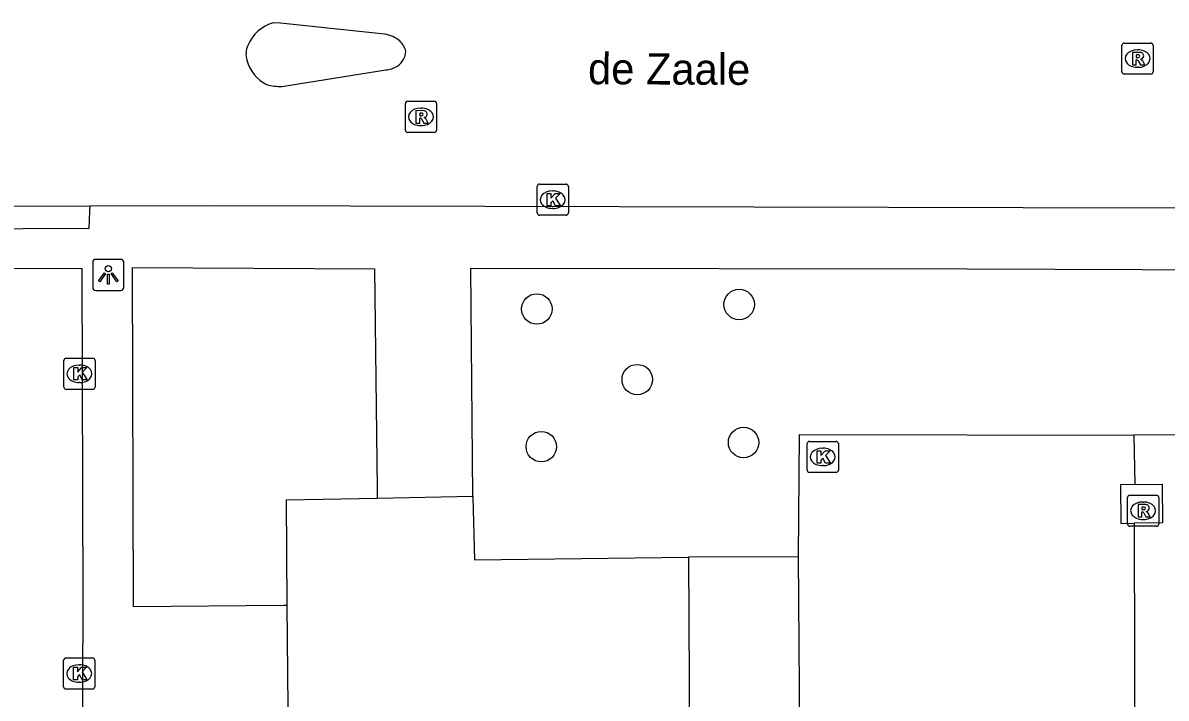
# Model space of a CAD drawing. Extents: x 161477 to 163040, y 383680 to 384868.
# Drawn here: x 161812.22 to 161848.92, y 384356.35 to 384378.03 of the extents above; entities that cross this region are included whole.
import ezdxf

# ---------------------------------------------------------------- set-up
doc = ezdxf.new("R2010")
doc.units = 0
for name, color, linetype in [('IMGEO_Boom', 7, 'Continuous'), ('IMGEO_Groenvoorziening', 7, 'Continuous'), ('IMGEO_Kolk', 7, 'Continuous'), ('IMGEO_Lichtpunt', 7, 'Continuous'), ('IMGEO_Openbare_ruimte_label', 7, 'Continuous'), ('IMGEO_Rijbaan_lokaal_open', 7, 'Continuous'), ('IMGEO_Rioolput', 7, 'Continuous'), ('IMGEO_Voetpad_gesloten', 7, 'Continuous'), ('IMGEO_Voetpad_op_trap', 7, 'Continuous'), ('IMGEO_Voetpad_open', 7, 'Continuous')]:
    doc.layers.add(name, color=color, linetype=linetype)

msp = doc.modelspace()

# ---------------------------------------------------------------- linework, layer by layer
at = {"layer": 'IMGEO_Boom'}
for centre in [(161835.213, 384368.986), (161828.719, 384368.843), (161831.942, 384366.577), (161828.862, 384364.424), (161835.355, 384364.556)]:
    msp.add_circle(centre, 0.489, dxfattribs=at)
at = {"layer": 'IMGEO_Groenvoorziening'}
msp.add_lwpolyline([(161866.104, 384364.813), (161847.882, 384364.794)], dxfattribs=at)
at = {"layer": 'IMGEO_Kolk'}
for p, q in [((161828.804, 384372.851), (161829.656, 384372.851)), ((161828.729, 384371.925), (161828.729, 384372.777)), ((161829.217, 384372.631), (161829.242, 384372.631)), ((161829.73, 384372.777), (161829.73, 384371.925)), ((161829.24, 384372.071), (161829.215, 384372.071)), ((161829.656, 384371.851), (161828.804, 384371.851)), ((161813.538, 384366.338), (161813.538, 384367.19)), ((161813.613, 384367.264), (161814.465, 384367.264)), ((161814.026, 384367.044), (161814.051, 384367.044)), ((161814.539, 384367.19), (161814.539, 384366.338)), ((161814.465, 384366.264), (161813.613, 384366.264)), ((161814.049, 384366.484), (161814.024, 384366.484)), ((161837.395, 384363.669), (161837.395, 384364.521)), ((161837.47, 384364.595), (161838.322, 384364.595)), ((161837.883, 384364.375), (161837.908, 384364.375)), ((161838.396, 384364.521), (161838.396, 384363.669)), ((161837.906, 384363.815), (161837.881, 384363.815)), ((161838.322, 384363.595), (161837.47, 384363.595)), ((161813.531, 384356.717), (161813.531, 384357.569)), ((161813.606, 384357.643), (161814.458, 384357.643)), ((161814.019, 384357.423), (161814.044, 384357.423)), ((161814.532, 384357.569), (161814.532, 384356.717)), ((161814.458, 384356.643), (161813.606, 384356.643)), ((161814.042, 384356.863), (161814.017, 384356.863))]:
    msp.add_line(p, q, dxfattribs=at)
for points in [[(161828.804, 384372.851), (161829.656, 384372.851)], [(161828.729, 384371.925), (161828.729, 384372.777)], [(161829.05, 384372.551), (161829.173, 384372.551), (161829.173, 384372.4), (161829.303, 384372.551), (161829.467, 384372.551), (161829.321, 384372.4), (161829.474, 384372.151), (161829.322, 384372.151), (161829.237, 384372.315), (161829.173, 384372.248), (161829.173, 384372.151), (161829.05, 384372.151), (161829.05, 384372.551)], [(161829.73, 384372.777), (161829.73, 384371.925)], [(161829.656, 384371.851), (161828.804, 384371.851)], [(161813.538, 384366.338), (161813.538, 384367.19)], [(161813.613, 384367.264), (161814.465, 384367.264)], [(161813.859, 384366.964), (161813.982, 384366.964), (161813.982, 384366.813), (161814.112, 384366.964), (161814.276, 384366.964), (161814.13, 384366.813), (161814.283, 384366.564), (161814.131, 384366.564), (161814.046, 384366.728), (161813.982, 384366.661), (161813.982, 384366.564), (161813.859, 384366.564), (161813.859, 384366.964)], [(161814.539, 384367.19), (161814.539, 384366.338)], [(161814.465, 384366.264), (161813.613, 384366.264)], [(161837.395, 384363.669), (161837.395, 384364.521)], [(161837.47, 384364.595), (161838.322, 384364.595)], [(161838.396, 384364.521), (161838.396, 384363.669)], [(161837.716, 384364.295), (161837.839, 384364.295), (161837.839, 384364.144), (161837.969, 384364.295), (161838.133, 384364.295), (161837.987, 384364.144), (161838.14, 384363.895), (161837.988, 384363.895), (161837.903, 384364.059), (161837.839, 384363.992), (161837.839, 384363.895), (161837.716, 384363.895), (161837.716, 384364.295)], [(161838.322, 384363.595), (161837.47, 384363.595)], [(161813.531, 384356.717), (161813.531, 384357.569)], [(161813.606, 384357.643), (161814.458, 384357.643)], [(161814.532, 384357.569), (161814.532, 384356.717)], [(161813.852, 384357.343), (161813.975, 384357.343), (161813.975, 384357.192), (161814.105, 384357.343), (161814.269, 384357.343), (161814.123, 384357.192), (161814.276, 384356.943), (161814.124, 384356.943), (161814.039, 384357.107), (161813.975, 384357.04), (161813.975, 384356.943), (161813.852, 384356.943), (161813.852, 384357.343)], [(161814.458, 384356.643), (161813.606, 384356.643)]]:
    msp.add_lwpolyline(points, dxfattribs=at)
for centre, start, end in [((161828.806, 384372.775), 91.552, 178.448), ((161828.806, 384372.775), 91.552, 178.448), ((161829.654, 384372.775), 1.552, 88.448), ((161829.654, 384372.775), 1.552, 88.448), ((161828.806, 384371.927), 181.552, 268.448), ((161828.806, 384371.927), 181.552, 268.448), ((161829.654, 384371.927), 271.552, 358.448), ((161829.654, 384371.927), 271.552, 358.448), ((161813.615, 384367.188), 91.552, 178.448), ((161813.615, 384367.188), 91.552, 178.448), ((161814.463, 384367.188), 1.552, 88.448), ((161814.463, 384367.188), 1.552, 88.448), ((161813.615, 384366.34), 181.552, 268.448), ((161813.615, 384366.34), 181.552, 268.448), ((161814.463, 384366.34), 271.552, 358.448), ((161814.463, 384366.34), 271.552, 358.448), ((161837.472, 384364.519), 91.552, 178.448), ((161837.472, 384364.519), 91.552, 178.448), ((161838.32, 384364.519), 1.552, 88.448), ((161838.32, 384364.519), 1.552, 88.448), ((161837.472, 384363.671), 181.552, 268.448), ((161837.472, 384363.671), 181.552, 268.448), ((161838.32, 384363.671), 271.552, 358.448), ((161838.32, 384363.671), 271.552, 358.448), ((161813.608, 384357.567), 91.552, 178.448), ((161813.608, 384357.567), 91.552, 178.448), ((161814.456, 384357.567), 1.552, 88.448), ((161814.456, 384357.567), 1.552, 88.448), ((161813.608, 384356.719), 181.552, 268.448), ((161813.608, 384356.719), 181.552, 268.448), ((161814.456, 384356.719), 271.552, 358.448), ((161814.456, 384356.719), 271.552, 358.448)]:
    msp.add_arc(centre, 0.0765, start, end, dxfattribs=at)
for centre, major_axis, ratio, start_param, end_param in [((161829.216, 384372.351), (-0.387, 0.002), 0.722429, 4.712389, 7.853982), ((161829.241, 384372.351), (-0.39, 0.002), 0.717154, 1.570796, 4.712389), ((161814.025, 384366.764), (-0.387, 0.002), 0.722429, 4.712389, 7.853982), ((161814.05, 384366.764), (-0.39, 0.002), 0.717154, 1.570796, 4.712389), ((161837.882, 384364.095), (-0.387, 0.002), 0.722429, 4.712389, 7.853982), ((161837.907, 384364.095), (-0.39, 0.002), 0.717154, 1.570796, 4.712389), ((161814.018, 384357.143), (-0.387, 0.002), 0.722429, 4.712389, 7.853982), ((161814.043, 384357.143), (-0.39, 0.002), 0.717154, 1.570796, 4.712389)]:
    msp.add_ellipse(centre, major_axis=major_axis, ratio=ratio, start_param=start_param, end_param=end_param, dxfattribs=at)
at = {"layer": 'IMGEO_Lichtpunt'}
for p, q in [((161814.466, 384370.342), (161814.466, 384369.535)), ((161814.466, 384370.342), (161814.466, 384369.535)), ((161815.368, 384370.437), (161814.56, 384370.437)), ((161815.368, 384370.437), (161814.56, 384370.437)), ((161815.462, 384369.535), (161815.462, 384370.342)), ((161815.462, 384369.535), (161815.462, 384370.342)), ((161814.56, 384369.441), (161815.368, 384369.441)), ((161814.56, 384369.441), (161815.368, 384369.441))]:
    msp.add_line(p, q, dxfattribs=at)
for points in [[(161814.84, 384370.006), (161814.879, 384369.978), (161814.691, 384369.716), (161814.653, 384369.743), (161814.84, 384370.006)], [(161814.942, 384369.958), (161814.989, 384369.958), (161814.989, 384369.636), (161814.942, 384369.636), (161814.942, 384369.958)], [(161815.052, 384369.978), (161815.09, 384370.005), (161815.277, 384369.743), (161815.238, 384369.715), (161815.052, 384369.978)]]:
    msp.add_lwpolyline(points, dxfattribs=at)
msp.add_circle((161814.965, 384370.14), 0.0994, dxfattribs=at)
for centre, start, end in [((161814.56, 384370.342), 90, 180), ((161814.56, 384370.342), 90, 180), ((161815.368, 384370.342), 0, 90), ((161815.368, 384370.342), 0, 90), ((161814.56, 384369.535), 180, 270), ((161814.56, 384369.535), 180, 270), ((161815.368, 384369.535), 270, 0), ((161815.368, 384369.535), 270, 360)]:
    msp.add_arc(centre, 0.0946, start, end, dxfattribs=at)
at = {"layer": 'IMGEO_Rijbaan_lokaal_open'}
for points in [[(161823.835, 384377.663), (161820.487, 384378.015), (161820.257, 384378.027)], [(161820.537, 384375.987), (161823.868, 384376.515)], [(161814.368, 384372.145), (161807.983, 384372.135)], [(161861.126, 384372.071), (161844.332, 384372.085), (161818.41, 384372.152), (161814.368, 384372.145)], [(161814.035, 384329.719), (161814.102, 384340.861), (161814.121, 384351.376), (161814.162, 384359.441), (161814.131, 384370.138), (161807.989, 384370.133)]]:
    msp.add_lwpolyline(points, dxfattribs=at)
for centre, radius, start, end in [((161820.613, 384376.806), 1.272, 106.2566, 156.888), ((161823.687, 384376.676), 0.998, 50.3941, 81.4633), ((161820.099, 384377.02), 0.716, 156.4919, 195.6095), ((161823.804, 384376.919), 0.739, 14.8896, 45.3685), ((161820.613, 384377.16), 1.249, 195.4874, 243.0755), ((161823.868, 384377.17), 0.653, 305.2923, 354.6184), ((161823.753, 384377.513), 1.005, 276.5601, 299.3038), ((161820.48, 384377.543), 1.557, 253.9011, 272.1085)]:
    msp.add_arc(centre, radius, start, end, dxfattribs=at)
at = {"layer": 'IMGEO_Rioolput'}
for p, q in [((161847.499, 384376.454), (161847.499, 384377.306)), ((161847.574, 384377.38), (161848.426, 384377.38)), ((161848.5, 384377.306), (161848.5, 384376.454)), ((161847.987, 384377.16), (161848.012, 384377.16)), ((161848.01, 384376.6), (161847.985, 384376.6)), ((161848.426, 384376.38), (161847.574, 384376.38)), ((161824.499, 384374.584), (161824.499, 384375.436)), ((161824.574, 384375.51), (161825.426, 384375.51)), ((161825.5, 384375.436), (161825.5, 384374.584)), ((161824.987, 384375.29), (161825.012, 384375.29)), ((161825.01, 384374.73), (161824.985, 384374.73)), ((161825.426, 384374.51), (161824.574, 384374.51)), ((161847.678, 384361.942), (161847.678, 384362.794)), ((161847.753, 384362.868), (161848.605, 384362.868)), ((161848.166, 384362.648), (161848.191, 384362.648)), ((161848.679, 384362.794), (161848.679, 384361.942)), ((161848.605, 384361.868), (161847.753, 384361.868)), ((161848.189, 384362.088), (161848.164, 384362.088))]:
    msp.add_line(p, q, dxfattribs=at)
for points in [[(161847.499, 384376.454), (161847.499, 384377.306)], [(161847.574, 384377.38), (161848.426, 384377.38)], [(161848.5, 384377.306), (161848.5, 384376.454)], [(161848.088, 384377.078), (161847.836, 384377.08), (161847.836, 384376.68)], [(161847.836, 384376.68), (161847.96, 384376.68), (161847.96, 384376.842), (161847.971, 384376.842)], [(161848.014, 384376.999), (161847.96, 384376.999), (161847.96, 384376.918)], [(161847.96, 384376.918), (161848.012, 384376.918)], [(161848.018, 384376.813), (161848.089, 384376.68), (161848.229, 384376.68), (161848.164, 384376.806)], [(161848.426, 384376.38), (161847.574, 384376.38)], [(161824.499, 384374.584), (161824.499, 384375.436)], [(161824.574, 384375.51), (161825.426, 384375.51)], [(161825.5, 384375.436), (161825.5, 384374.584)], [(161825.088, 384375.208), (161824.836, 384375.21), (161824.836, 384374.81)], [(161825.014, 384375.129), (161824.96, 384375.129), (161824.96, 384375.048)], [(161824.96, 384375.048), (161825.012, 384375.048)], [(161824.836, 384374.81), (161824.96, 384374.81), (161824.96, 384374.972), (161824.971, 384374.972)], [(161825.018, 384374.943), (161825.089, 384374.81), (161825.229, 384374.81), (161825.164, 384374.936)], [(161825.426, 384374.51), (161824.574, 384374.51)], [(161847.678, 384361.942), (161847.678, 384362.794)], [(161847.753, 384362.868), (161848.605, 384362.868)], [(161848.267, 384362.566), (161848.015, 384362.568), (161848.015, 384362.168)], [(161848.679, 384362.794), (161848.679, 384361.942)], [(161848.015, 384362.168), (161848.139, 384362.168), (161848.139, 384362.33), (161848.15, 384362.33)], [(161848.193, 384362.487), (161848.139, 384362.487), (161848.139, 384362.406)], [(161848.139, 384362.406), (161848.191, 384362.406)], [(161848.197, 384362.301), (161848.268, 384362.168), (161848.408, 384362.168), (161848.343, 384362.294)], [(161848.605, 384361.868), (161847.753, 384361.868)]]:
    msp.add_lwpolyline(points, dxfattribs=at)
for centre, radius, start, end in [((161847.576, 384377.304), 0.0765, 91.552, 178.448), ((161847.576, 384377.304), 0.0765, 91.552, 178.448), ((161848.424, 384377.304), 0.0765, 1.552, 88.448), ((161848.424, 384377.304), 0.0765, 1.552, 88.448), ((161847.97, 384376.789), 0.0533, 26.0293, 88.6989), ((161847.996, 384377.107), 0.19, 274.7715, 282.9687), ((161848.02, 384376.903), 0.0964, 77.0061, 93.1865), ((161848.034, 384376.96), 0.0378, 276.6634, 79.6772), ((161848.087, 384376.968), 0.109, 350.3612, 89.416), ((161848.085, 384376.968), 0.112, 277.5842, 350.9817), ((161848.069, 384376.753), 0.108, 29.5134, 73.7905), ((161847.576, 384376.456), 0.0765, 181.552, 268.448), ((161847.576, 384376.456), 0.0765, 181.552, 268.448), ((161848.424, 384376.456), 0.0765, 271.552, 358.448), ((161848.424, 384376.456), 0.0765, 271.552, 358.448), ((161824.576, 384375.434), 0.0765, 91.552, 178.448), ((161824.576, 384375.434), 0.0765, 91.552, 178.448), ((161825.424, 384375.434), 0.0765, 1.552, 88.448), ((161825.424, 384375.434), 0.0765, 1.552, 88.448), ((161824.996, 384375.237), 0.19, 274.7715, 282.9687), ((161825.02, 384375.033), 0.0964, 77.0061, 93.1865), ((161825.034, 384375.09), 0.0378, 276.6634, 79.6772), ((161825.087, 384375.098), 0.109, 350.3612, 89.416), ((161825.085, 384375.098), 0.112, 277.5842, 350.9817), ((161825.069, 384374.883), 0.108, 29.5134, 73.7905), ((161824.97, 384374.919), 0.0533, 26.0293, 88.6989), ((161824.576, 384374.586), 0.0765, 181.552, 268.448), ((161824.576, 384374.586), 0.0765, 181.552, 268.448), ((161825.424, 384374.586), 0.0765, 271.552, 358.448), ((161825.424, 384374.586), 0.0765, 271.552, 358.448), ((161847.755, 384362.792), 0.0765, 91.552, 178.448), ((161847.755, 384362.792), 0.0765, 91.552, 178.448), ((161848.266, 384362.456), 0.109, 350.3612, 89.416), ((161848.603, 384362.792), 0.0765, 1.552, 88.448), ((161848.603, 384362.792), 0.0765, 1.552, 88.448), ((161848.149, 384362.277), 0.0533, 26.0293, 88.6989), ((161848.175, 384362.595), 0.19, 274.7715, 282.9687), ((161848.199, 384362.391), 0.0964, 77.0061, 93.1865), ((161848.213, 384362.448), 0.0378, 276.6634, 79.6772), ((161848.264, 384362.456), 0.112, 277.5842, 350.9817), ((161848.248, 384362.241), 0.108, 29.5134, 73.7905), ((161847.755, 384361.944), 0.0765, 181.552, 268.448), ((161847.755, 384361.944), 0.0765, 181.552, 268.448), ((161848.603, 384361.944), 0.0765, 271.552, 358.448), ((161848.603, 384361.944), 0.0765, 271.552, 358.448)]:
    msp.add_arc(centre, radius, start, end, dxfattribs=at)
for centre, major_axis, ratio, start_param, end_param in [((161847.986, 384376.88), (-0.387, 0.002), 0.722429, 4.712389, 7.853982), ((161848.011, 384376.88), (-0.39, 0.002), 0.717154, 1.570796, 4.712389), ((161824.986, 384375.01), (-0.387, 0.002), 0.722429, 4.712389, 7.853982), ((161825.011, 384375.01), (-0.39, 0.002), 0.717154, 1.570796, 4.712389), ((161848.165, 384362.368), (-0.387, 0.002), 0.722429, 4.712389, 7.853982), ((161848.19, 384362.368), (-0.39, 0.002), 0.717154, 1.570796, 4.712389)]:
    msp.add_ellipse(centre, major_axis=major_axis, ratio=ratio, start_param=start_param, end_param=end_param, dxfattribs=at)
at = {"layer": 'IMGEO_Voetpad_gesloten'}
for points in [[(161847.914, 384363.209), (161847.448, 384363.203), (161847.463, 384361.963), (161847.888, 384361.969)], [(161847.914, 384363.209), (161848.788, 384363.22), (161848.803, 384361.98), (161847.888, 384361.969)]]:
    msp.add_lwpolyline(points, dxfattribs=at)
at = {"layer": 'IMGEO_Voetpad_op_trap'}
msp.add_lwpolyline([(161837.12, 384360.892), (161833.591, 384360.874)], dxfattribs=at)
at = {"layer": 'IMGEO_Voetpad_open'}
for points in [[(161814.368, 384372.145), (161814.361, 384371.982), (161814.335, 384371.427), (161807.978, 384371.397)], [(161820.711, 384359.33), (161820.602, 384359.329), (161815.772, 384359.283), (161815.746, 384370.177), (161823.509, 384370.128), (161823.592, 384363.058), (161823.595, 384362.772)], [(161826.665, 384362.833), (161826.596, 384370.149), (161842.531, 384370.13), (161859.393, 384370.069), (161859.337, 384369.912), (161860.901, 384369.01)], [(161837.12, 384360.892), (161837.147, 384364.815), (161847.882, 384364.794)], [(161847.882, 384364.794), (161847.914, 384363.209)], [(161820.711, 384359.33), (161820.686, 384362.714), (161823.595, 384362.772)], [(161823.595, 384362.772), (161826.665, 384362.833)], [(161826.665, 384362.833), (161826.665, 384362.807), (161826.719, 384360.791), (161833.591, 384360.874)], [(161847.888, 384361.969), (161847.888, 384361.652), (161847.908, 384353.974)], [(161833.591, 384360.874), (161833.626, 384352.84), (161828.61, 384352.789)], [(161839.159, 384353.911), (161837.171, 384353.896), (161837.12, 384360.892)], [(161820.736, 384356.063), (161820.711, 384359.33)]]:
    msp.add_lwpolyline(points, dxfattribs=at)

# ---------------------------------------------------------------- texts
at = {"layer": 'IMGEO_Openbare_ruimte_label'}
msp.add_text('de Zaale', height=1, rotation=359.7135, dxfattribs=at).set_placement((161830.361, 384376.06))

doc.saveas('drawing.dxf')
